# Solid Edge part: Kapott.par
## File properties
Author: Türk
Template: iso part.par
Last saved by: Türk
Revision: 19
Application: Solid Edge
Accuracy: 0,990
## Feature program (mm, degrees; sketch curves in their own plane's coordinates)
base feature "unnamed BaseFeature 1"
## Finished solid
Body 1: sheet body, 5 faces, 12 edges, 8 vertices.
  Faces by surface: spline 5
  Edges by curve: curve on surface 8, intersection 2, spline 2
Body 2: solid body, 66 faces, 189 edges, 123 vertices.
  Faces by surface: plane 23, blend 14, cylinder 12, spline 9, offset 4, swept 4
  Edges by curve: intersection 112, line 50, curve on surface 12, circle 10, ellipse 4, spline 1
Body 3: sheet body, 2 faces, 7 edges, 6 vertices.
  Faces by surface: spline 2
  Edges by curve: intersection 4, spline 3
Body 4: sheet body, 1 face, 4 edges, 4 vertices.
  Faces by surface: swept 1
  Edges by curve: line 2, spline 2
Bounding box of the edges (mm; curved faces can reach further): 1263.302 x 1265.012 x 332.055, from (-631.6508, -400, 340.6914) to (631.6508, 865.0119, 672.746).
Cylindrical faces by radius (mm): R10 x6, R15 x4, R25 x2
Planar faces by outward normal: +x 3, +y 3, +z 1, -x 3, -y 3, -z 1, oblique 9
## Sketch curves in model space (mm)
line (-300, -399.0156, 351.3743) -> (-300, -399.0156, 341.3743)
line (300, -399.0156, 341.3743) -> (300, -399.0156, 351.3743)
spline (-525.7632, 0, 417.8427) -> (-271.3913, 0, 444.0697) -> (0, 0, 455.7985)
spline (0, 809.9999, 450) -> (0, 197.4055, 464.3314) -> (0, -400, 346.028)
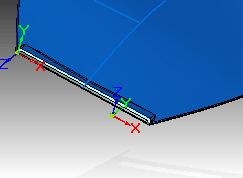
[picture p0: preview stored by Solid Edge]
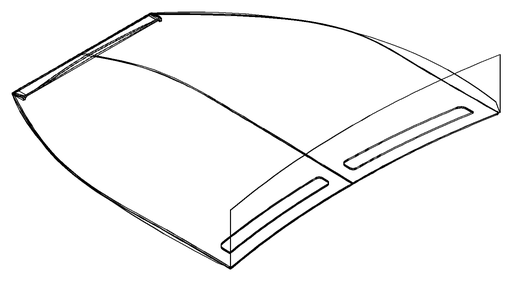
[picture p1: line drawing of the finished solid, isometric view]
